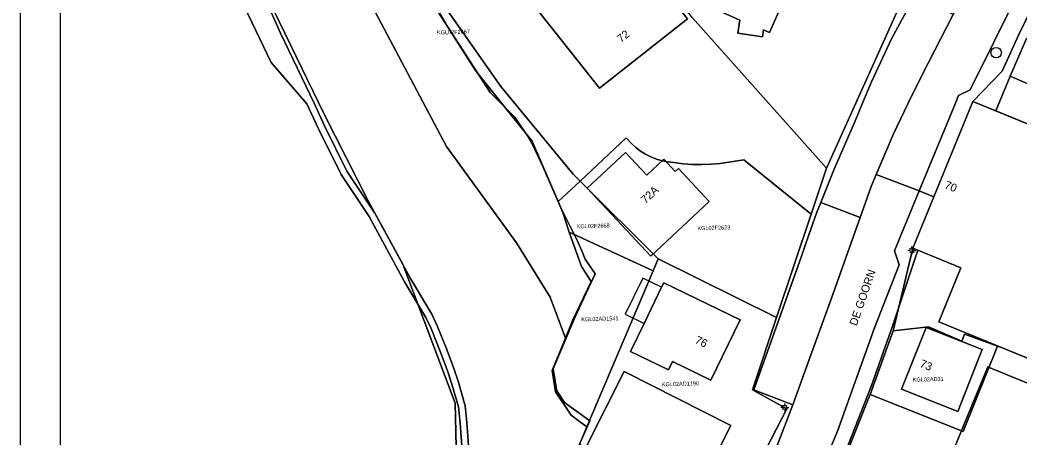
# Model space of a CAD drawing. Extents: x 124901 to 125496, y 515369 to 515789.
# Drawn here: x 124901.4 to 125026.4, y 515458.2 to 515510.4 of the extents above; entities that cross this region are included whole.
import ezdxf

# ---------------------------------------------------------------- set-up
doc = ezdxf.new("R2010")
doc.units = 0
for name, color, linetype in [('Alg Kaders', 7, 'Continuous'), ('Gebouw', 7, 'Continuous'), ('Lichtmast', 7, 'Continuous'), ('Luifel', 7, 'Continuous'), ('Onbegroeid terrein', 7, 'Continuous'), ('Parkeren', 7, 'Continuous'), ('Perceelnummers', 7, 'Continuous'), ('Perceelsgrenzen', 7, 'Continuous'), ('Putten', 7, 'Continuous'), ('Scheiding', 7, 'Continuous'), ('Teksten', 7, 'Continuous'), ('Vegetatie', 7, 'Continuous'), ('Voetpad', 7, 'Continuous'), ('Water', 7, 'Continuous'), ('Wegen lokale weg', 7, 'Continuous')]:
    doc.layers.add(name, color=color, linetype=linetype)

msp = doc.modelspace()

# ---------------------------------------------------------------- linework, layer by layer
at = {"layer": 'Alg Kaders'}
for points in [[(125495.93, 515789.04), (124901.43, 515789.04), (124901.43, 515368.54), (125495.93, 515368.54)], [(125490.93, 515784.04), (124906.43, 515784.04), (124906.43, 515373.54), (125490.93, 515373.54)]]:
    msp.add_lwpolyline(points, close=True, dxfattribs=at)
at = {"layer": 'Gebouw'}
for points in [[(124988.97, 515511.42), (124991.38, 515510.36), (124991.13, 515508.73), (124994.2, 515508.27), (124994.33, 515509.14), (124995.08, 515508.81), (124998.36, 515516.25), (124996.66, 515517), (124998.69, 515521.62), (124991.03, 515525), (124988.08, 515518.32), (124991.37, 515516.87)], [(124964.31, 515514.87), (124965.22, 515513.72), (124964.77, 515513.36), (124973.83, 515501.87), (124984.84, 515510.54), (124975.96, 515521.82), (124972.22, 515518.88), (124970.17, 515521.49), (124965.19, 515517.56), (124966.16, 515516.33)], [(125015.62, 515488.3), (125013, 515481.9), (125013.63, 515481.64), (125018.98, 515479.45), (125016.22, 515472.7), (125024.05, 515469.5), (125032.71, 515465.95), (125036.74, 515464.3), (125038.93, 515469.64), (125039.85, 515469.26), (125045.63, 515483.36), (125040.75, 515485.36), (125043.05, 515490.98), (125023.37, 515499.04), (125020.5, 515500.22)], [(124972.31, 515489.39), (124980.23, 515480.88), (124987.54, 515487.7), (124983.69, 515491.83), (124983.29, 515491.46), (124981.86, 515492.99), (124979.74, 515491.02), (124977.1, 515493.85)], [(124987.75, 515465.41), (124991.4, 515472.93), (124981.86, 515477.56), (124981.59, 515477.02), (124979.41, 515472.51), (124977.71, 515469.01), (124982.44, 515466.71), (124982.94, 515467.74)], [(125014.66, 515471.99), (125011.58, 515464.31), (125018.6, 515461.5), (125021.66, 515469.23)], [(125016.87, 515453.78), (125028.05, 515449.2), (125028.46, 515449.58), (125031.09, 515448.42), (125030.07, 515446.1), (125056, 515434.66), (125064.38, 515453.66), (125039.12, 515464.8), (125038.12, 515462.55), (125034.18, 515464.68), (125033.33, 515462.6), (125031.62, 515463.3), (125022.95, 515466.82), (125022.34, 515467.07)], [(124976.9, 515466.49), (124972.29, 515457.36), (124973.15, 515456.93), (124985.62, 515450.63), (124990.23, 515459.76)]]:
    msp.add_lwpolyline(points, close=True, dxfattribs=at)
msp.add_lwpolyline([(125033.82, 515518.55), (125028.97, 515507.31), (125027.18, 515508.08), (125025.14, 515503.35), (125029.68, 515501.39), (125030.08, 515502.31), (125036.51, 515499.54), (125036.09, 515498.58), (125038.45, 515497.57), (125038.84, 515498.45), (125046.48, 515495.15), (125046.09, 515494.26), (125048.68, 515493.14), (125049.1, 515494.12), (125055.97, 515491.15), (125061.86, 515489.39), (125068.33, 515492.29), (125071.39, 515498.74), (125068.94, 515505.52), (125065.48, 515507.51), (125065.75, 515508.37), (125064.94, 515509.67), (125062.61, 515510.67)], dxfattribs=at)
at = {"layer": 'Lichtmast'}
for p, q in [((125012.87, 515481.9), (125012.87, 515482.1)), ((125012.57, 515481.6), (125012.37, 515481.6)), ((125012.66, 515481.81), (125012.59, 515481.89)), ((125012.66, 515481.39), (125012.59, 515481.32)), ((125012.87, 515481.3), (125012.87, 515481.1)), ((125013.08, 515481.81), (125013.15, 515481.89)), ((125013.08, 515481.39), (125013.15, 515481.32)), ((125013.17, 515481.6), (125013.37, 515481.6)), ((124996.76, 515462.23), (124996.69, 515462.3)), ((124996.98, 515462.32), (124996.98, 515462.52)), ((124997.19, 515462.23), (124997.26, 515462.3)), ((124996.68, 515462.02), (124996.48, 515462.02)), ((124996.76, 515461.81), (124996.69, 515461.73)), ((124996.98, 515461.72), (124996.98, 515461.52)), ((124997.19, 515461.81), (124997.26, 515461.73)), ((124997.28, 515462.02), (124997.48, 515462.02))]:
    msp.add_line(p, q, dxfattribs=at)
for centre in [(125012.87, 515481.6), (124996.98, 515462.02)]:
    msp.add_circle(centre, 0.25, dxfattribs=at)
at = {"layer": 'Luifel'}
msp.add_lwpolyline([(124977.06, 515473.65), (124979.41, 515472.51), (124981.59, 515477.02), (124979.25, 515478.15)], close=True, dxfattribs=at)
at = {"layer": 'Onbegroeid terrein'}
for points in [[(124991.38, 515510.36), (124988.97, 515511.42), (124991.37, 515516.87), (124988.08, 515518.32), (124991.03, 515525), (124998.69, 515521.62), (124996.66, 515517), (124998.36, 515516.25), (124995.08, 515508.81), (124994.33, 515509.14), (124994.2, 515508.27), (124991.13, 515508.73)], [(124965.22, 515513.72), (124964.31, 515514.87), (124966.16, 515516.33), (124965.19, 515517.56), (124970.17, 515521.49), (124972.22, 515518.88), (124975.96, 515521.82), (124984.84, 515510.54), (124973.83, 515501.87), (124964.77, 515513.36)], [(124980.23, 515480.88), (124972.31, 515489.39), (124977.1, 515493.85), (124979.74, 515491.02), (124981.86, 515492.99), (124983.29, 515491.46), (124983.69, 515491.83), (124987.54, 515487.7)], [(124991.4, 515472.93), (124987.75, 515465.41), (124982.94, 515467.74), (124982.44, 515466.71), (124977.71, 515469.01), (124979.41, 515472.51), (124981.59, 515477.02), (124981.86, 515477.56)], [(125011.58, 515464.31), (125014.66, 515471.99), (125021.66, 515469.23), (125018.6, 515461.5)], [(125028.05, 515449.2), (125016.87, 515453.78), (125022.34, 515467.07), (125022.95, 515466.82), (125031.62, 515463.3), (125033.33, 515462.6), (125034.18, 515464.68), (125038.12, 515462.55), (125039.12, 515464.8), (125064.38, 515453.66), (125056, 515434.66), (125030.07, 515446.1), (125031.09, 515448.42), (125028.46, 515449.58)], [(124986.4, 515450.24), (124981.86, 515441.26), (124968.62, 515447.95), (124973.15, 515456.93), (124972.29, 515457.36), (124976.9, 515466.49), (124990.23, 515459.76), (124985.62, 515450.63)]]:
    msp.add_lwpolyline(points, close=True, dxfattribs=at)
for points in [[(124952.34, 515513.49), (124960.19, 515501.34), (124961.49, 515500), (124961.86, 515499.62), (124963.27, 515498.23), (124964.01, 515497.13), (124964.84, 515495.93), (124965.56, 515494.65), (124966.74, 515492.11), (124968.01, 515489.21), (124969.03, 515486.85), (124970.16, 515484.61), (124971.03, 515482.9), (124971.73, 515481.37), (124972.05, 515480.54), (124973.31, 515478.71), (124970.78, 515473.33), (124968.06, 515466.82), (124968.49, 515464.08), (124969.48, 515462.64), (124972.63, 515460.34), (124969.79, 515453.93)], [(124996.04, 515457.25), (124998.01, 515462.33), (124993.12, 515464.2), (124999.07, 515480.89), (125000, 515483.55), (125001, 515486.4), (125001.48, 515487.6), (125003.15, 515491.77), (125005.69, 515497.59), (125006.71, 515500), (125007.82, 515502.64), (125010.33, 515508.03), (125013.25, 515513.43)], [(125032.71, 515465.95), (125024.05, 515469.5), (125016.22, 515472.7), (125018.98, 515479.45), (125013.63, 515481.64), (125010.49, 515472.27), (125007.84, 515464.74), (125004.5, 515456.26), (125003.05, 515452.56), (125000.21, 515446.59), (125000, 515446.18), (124996.84, 515440.14), (124993.97, 515434.64), (124993.94, 515434.57), (124990.96, 515429.02), (124990.09, 515427.23), (125008.09, 515417.98), (125008.07, 515417.92), (125020.57, 515411.85), (125020.42, 515411.55), (125029.53, 515407.12)]]:
    msp.add_lwpolyline(points, dxfattribs=at)
at = {"layer": 'Parkeren'}
for points in [[(125012.42, 515500), (125014.09, 515503.45), (125018.03, 515511.05), (125013.25, 515513.43), (125010.33, 515508.03), (125007.82, 515502.64), (125006.71, 515500), (125005.69, 515497.59), (125003.15, 515491.77), (125001.48, 515487.6), (125006.39, 515485.74), (125007.76, 515489.59), (125008.4, 515491.08), (125010.58, 515496.17)], [(124999.07, 515480.89), (124993.12, 515464.2), (124998.01, 515462.33), (125000, 515467.86), (125002.81, 515475.67), (125006.39, 515485.74), (125001.48, 515487.6), (125001, 515486.4), (125000, 515483.55)]]:
    msp.add_lwpolyline(points, close=True, dxfattribs=at)
at = {"layer": 'Perceelsgrenzen'}
for points in [[(124906.43, 515606.91), (124921.33, 515576.99), (124930.94, 515557.71), (124940.5, 515538.53), (124943.74, 515529.11), (124948.77, 515520.44), (124953.68, 515511.61), (124954.97, 515509.34), (124958.34, 515504.07), (124962.67, 515498.66), (124965.42, 515495.25), (124968.66, 515487.72), (124969.25, 515486.36), (124970.05, 515483.9), (124971.6, 515479.59), (124972.78, 515477.75), (124970.52, 515472.93), (124969.58, 515470.64), (124967.68, 515475.76), (124963.46, 515482.58), (124954.71, 515494.57), (124906.43, 515585.66)], [(124906.43, 515585.66), (124954.71, 515494.57), (124963.46, 515482.58), (124967.68, 515475.76), (124969.58, 515470.64), (124967.92, 515466.62), (124968.35, 515463.96), (124970.29, 515461.05), (124971.18, 515460.39), (124972.27, 515459.58), (124971.34, 515457.4)], [(124906.43, 515396.39), (124928.22, 515415.41), (124937.62, 515423.9), (124948.4, 515434.41), (124953.91, 515444.6), (124956.01, 515453.43), (124955.8, 515462.55), (124949.28, 515479.9), (124944.99, 515487.71), (124939.45, 515498.62), (124906.43, 515566.53)], [(124906.43, 515566.53), (124939.45, 515498.62), (124944.99, 515487.71), (124949.28, 515479.9), (124955.8, 515462.55), (124956.01, 515453.43), (124953.91, 515444.6), (124948.4, 515434.41), (124937.62, 515423.9), (124928.22, 515415.41), (124906.43, 515396.39)], [(125039.25, 515535.31), (125026.22, 515508.58), (125024.14, 515504), (125020.5, 515500.22), (125013, 515481.9), (125010.52, 515471.57), (125007.65, 515463.62), (125007.63, 515463.55), (125004.74, 515456.35)], [(125094.17, 515514.63), (125090.88, 515508.4), (125088.35, 515503.32), (125080.95, 515487.83), (125074.8, 515474.79), (125072.92, 515470.76), (125070.56, 515465.28), (125067.85, 515459.25), (125065.82, 515454.22), (125065.75, 515454), (125039.06, 515466.79), (125048.34, 515489.08), (125043.05, 515490.98), (125020.5, 515500.22), (125024.14, 515504), (125026.22, 515508.58), (125039.25, 515535.31)], [(124963.73, 515373.54), (124963.84, 515377.36), (124964.18, 515380.8), (124964.18, 515380.86), (124965.45, 515385.83), (124966.31, 515389.11), (124966.49, 515389.7), (124973.77, 515412.76), (124973.81, 515412.89), (124982.49, 515430.39), (124983.37, 515431.98), (124986.36, 515437.42), (124985.08, 515438.27), (124990.04, 515447.9), (124997.23, 515461.84), (124992.97, 515464.22), (124995.97, 515473.23), (125000.28, 515486.13), (125002.19, 515491.87), (125002.22, 515491.96), (125012.3, 515514.36)], [(124985.45, 515510.65), (125002.19, 515491.87), (125000.28, 515486.13), (124991.85, 515492.92), (124988.93, 515492.47), (124987.77, 515492.37), (124986.6, 515492.33), (124985.44, 515492.35), (124984.28, 515492.43), (124983.12, 515492.58), (124982.39, 515492.66), (124981.66, 515492.8), (124980.95, 515493.01), (124980.26, 515493.29), (124979.6, 515493.62), (124978.97, 515494.02), (124978.38, 515494.47), (124977.84, 515494.97), (124977.18, 515495.65), (124971.41, 515490.27), (124970.53, 515491.15), (124961.52, 515502.09), (124954.25, 515512.39)]]:
    msp.add_lwpolyline(points, dxfattribs=at)
for points in [[(124940.5, 515538.53), (124945.57, 515528.36), (124949.61, 515520.93), (124954.25, 515512.39), (124961.52, 515502.09), (124970.53, 515491.15), (124971.41, 515490.27), (124968.66, 515487.72), (124965.42, 515495.25), (124962.67, 515498.66), (124958.34, 515504.07), (124954.97, 515509.34), (124953.68, 515511.61), (124948.77, 515520.44), (124943.74, 515529.11)], [(125002.19, 515491.87), (124985.45, 515510.65), (124966.12, 515535.43), (124971.71, 515537.65), (125004.29, 515523.22), (125002.95, 515519.51), (125007.38, 515516.88), (125012.3, 515514.36), (125002.22, 515491.96)], [(125010.52, 515471.57), (125013, 515481.9), (125020.5, 515500.22), (125043.05, 515490.98), (125048.34, 515489.08), (125039.06, 515466.79), (125037.82, 515463.73), (125036.74, 515464.3), (125024.05, 515469.5), (125023.57, 515469.67), (125019.45, 515471.18), (125019.12, 515470.3), (125014.96, 515472.07)], [(124988.93, 515492.47), (124991.85, 515492.92), (125000.28, 515486.13), (124995.97, 515473.23), (124981.16, 515480.56), (124971.41, 515490.27), (124977.18, 515495.65), (124977.84, 515494.97), (124978.38, 515494.47), (124978.97, 515494.02), (124979.6, 515493.62), (124980.26, 515493.29), (124980.95, 515493.01), (124981.66, 515492.8), (124982.39, 515492.66), (124983.12, 515492.58), (124984.28, 515492.43), (124985.44, 515492.35), (124986.6, 515492.33), (124987.77, 515492.37)], [(124968.66, 515487.72), (124971.41, 515490.27), (124981.16, 515480.56), (124980.54, 515479.08), (124970.05, 515483.9), (124969.25, 515486.36)], [(124972.27, 515459.58), (124971.18, 515460.39), (124970.29, 515461.05), (124968.35, 515463.96), (124967.92, 515466.62), (124969.58, 515470.64), (124970.52, 515472.93), (124972.78, 515477.75), (124971.6, 515479.59), (124970.05, 515483.9), (124980.54, 515479.08)], [(124980.54, 515479.08), (124981.16, 515480.56), (124995.97, 515473.23), (124992.97, 515464.22), (124997.23, 515461.84), (124990.04, 515447.9), (124986.17, 515449.95), (124972.98, 515456.87), (124972.8, 515456.58), (124971.93, 515457.03), (124971.34, 515457.4), (124972.27, 515459.58)], [(125010.52, 515471.57), (125014.96, 515472.07), (125019.12, 515470.3), (125019.45, 515471.18), (125023.57, 515469.67), (125019.29, 515459), (125007.65, 515463.62)], [(125056.93, 515433.58), (125016.13, 515451.95), (125015.89, 515451.35), (125004.74, 515456.35), (125007.63, 515463.55), (125007.65, 515463.62), (125019.29, 515459), (125023.57, 515469.67), (125024.05, 515469.5), (125036.74, 515464.3), (125037.82, 515463.73), (125039.06, 515466.79), (125065.75, 515454), (125065.59, 515453.4), (125061.11, 515443.41), (125057.67, 515435.37)]]:
    msp.add_lwpolyline(points, close=True, dxfattribs=at)
at = {"layer": 'Putten'}
msp.add_circle((125023.4, 515506.3), 0.65, dxfattribs=at)
at = {"layer": 'Scheiding'}
msp.add_lwpolyline([(124966.98, 515447.52), (124969.79, 515453.93), (124972.63, 515460.34), (124969.48, 515462.64), (124968.49, 515464.08), (124968.06, 515466.82), (124970.78, 515473.33), (124973.31, 515478.71)], dxfattribs=at)
at = {"layer": 'Vegetatie'}
msp.add_lwpolyline([(124956.62, 515457.22), (124956.42, 515460.06), (124956.2, 515462.07), (124955.4, 515464.93), (124954.79, 515466.7), (124953.89, 515469.14), (124952.78, 515471.88), (124952.13, 515473.24), (124949.48, 515477.68), (124945.04, 515485.85), (124941.55, 515491.08), (124938.72, 515496.79), (124937.28, 515499.92), (124932.82, 515505.08), (124926.99, 515517.25)], dxfattribs=at)
at = {"layer": 'Voetpad'}
for points in [[(125026.09, 515513.69), (125020.14, 515501.66), (125018.7, 515500.95), (125018.3, 515500), (125013.79, 515489.05), (125015.62, 515488.3), (125020.5, 515500.22), (125023.37, 515499.04), (125025.14, 515503.35), (125027.18, 515508.08), (125028.97, 515507.31), (125033.82, 515518.55)], [(125029.68, 515501.39), (125025.14, 515503.35), (125023.37, 515499.04), (125043.05, 515490.98)], [(125004.5, 515456.26), (125007.84, 515464.74), (125010.49, 515472.27), (125013.63, 515481.64), (125013, 515481.9), (125015.62, 515488.3), (125013.79, 515489.05), (125010.7, 515481.55), (125011.28, 515479.8), (125008.21, 515471.97), (125003.56, 515459.06), (125000.61, 515451.92)]]:
    msp.add_lwpolyline(points, dxfattribs=at)
at = {"layer": 'Water'}
for points in [[(124922.55, 515534.32), (124933.98, 515508.72), (124938.17, 515500), (124939.47, 515497.15), (124942.28, 515491.5), (124945.76, 515486.28), (124950.21, 515478.09), (124952.87, 515473.64), (124953.55, 515472.22), (124954.68, 515469.44), (124955.58, 515466.99), (124956.2, 515465.18), (124957.03, 515462.23), (124957.26, 515460.14), (124957.47, 515457.22)], [(124957.47, 515457.22), (124957.26, 515460.14), (124957.03, 515462.23), (124956.2, 515465.18), (124955.58, 515466.99), (124954.68, 515469.44), (124953.55, 515472.22), (124952.87, 515473.64), (124950.21, 515478.09), (124945.76, 515486.28), (124942.28, 515491.5), (124939.47, 515497.15), (124938.17, 515500), (124933.98, 515508.72), (124922.55, 515534.32)], [(124926.99, 515517.25), (124932.82, 515505.08), (124937.28, 515499.92), (124938.72, 515496.79), (124941.55, 515491.08), (124945.04, 515485.85), (124949.48, 515477.68), (124952.13, 515473.24), (124952.78, 515471.88), (124953.89, 515469.14), (124954.79, 515466.7), (124955.4, 515464.93), (124956.2, 515462.07), (124956.42, 515460.06), (124956.62, 515457.22)], [(124969.79, 515453.93), (124972.63, 515460.34), (124969.48, 515462.64), (124968.49, 515464.08), (124968.06, 515466.82), (124970.78, 515473.33), (124973.31, 515478.71), (124972.05, 515480.54), (124971.73, 515481.37), (124971.03, 515482.9), (124970.16, 515484.61), (124969.03, 515486.85), (124968.01, 515489.21), (124966.74, 515492.11), (124965.56, 515494.65), (124964.84, 515495.93), (124964.01, 515497.13), (124963.27, 515498.23), (124961.86, 515499.62), (124961.49, 515500), (124960.19, 515501.34), (124952.34, 515513.49)]]:
    msp.add_lwpolyline(points, dxfattribs=at)
at = {"layer": 'Wegen lokale weg'}
msp.add_lwpolyline([(125026.09, 515513.69), (125036.24, 515534.14), (125042.97, 515547.8), (125049.31, 515560.25), (125043.54, 515563.11), (125043.15, 515562.12), (125041.65, 515558.67), (125041.16, 515557.7), (125035.4, 515546.43), (125024.23, 515523.14), (125019.65, 515514.19), (125018.59, 515512.14), (125018.03, 515511.05), (125014.09, 515503.45), (125012.42, 515500), (125010.58, 515496.17), (125008.4, 515491.08), (125013.79, 515489.05), (125018.3, 515500), (125018.7, 515500.95), (125020.14, 515501.66)], close=True, dxfattribs=at)
msp.add_lwpolyline([(125000.61, 515451.92), (125003.56, 515459.06), (125008.21, 515471.97), (125011.28, 515479.8), (125010.7, 515481.55), (125013.79, 515489.05), (125008.4, 515491.08), (125007.76, 515489.59), (125006.39, 515485.74), (125002.81, 515475.67), (125000, 515467.86), (124998.01, 515462.33), (124996.04, 515457.25)], dxfattribs=at)

# ---------------------------------------------------------------- texts
at = {"layer": 'Perceelnummers'}
for s, rotation, p in [('KGL02F2667', 1.6293, (124953.54, 515508.57)), ('KGL02F2668', 1.6295, (124971, 515484.36)), ('KGL02F2623', 1.6297, (124986.08, 515484.13)), ('KGL02AD1541', 1.8277, (124971.57, 515472.75)), ('KGL02AD31', 1.4318, (125012.97, 515465.23)), ('KGL02AD1190', 1.8278, (124981.63, 515464.64))]:
    msp.add_text(s, height=0.5, rotation=rotation, dxfattribs=at).set_placement(p)
at = {"layer": 'Teksten'}
for s, rotation, p in [('72', 38.2, (124976.52, 515507.5)), ('70', 337.7, (125016.86, 515489.42)), ('72A', 43, (124979.58, 515487.4)), ('DE GOORN', 70.9, (125005.97, 515472.13)), ('76', 334.1, (124985.68, 515470.1)), ('73', 338.2, (125013.77, 515467.11))]:
    msp.add_text(s, height=1, rotation=rotation, dxfattribs=at).set_placement(p)

doc.saveas('drawing.dxf')
